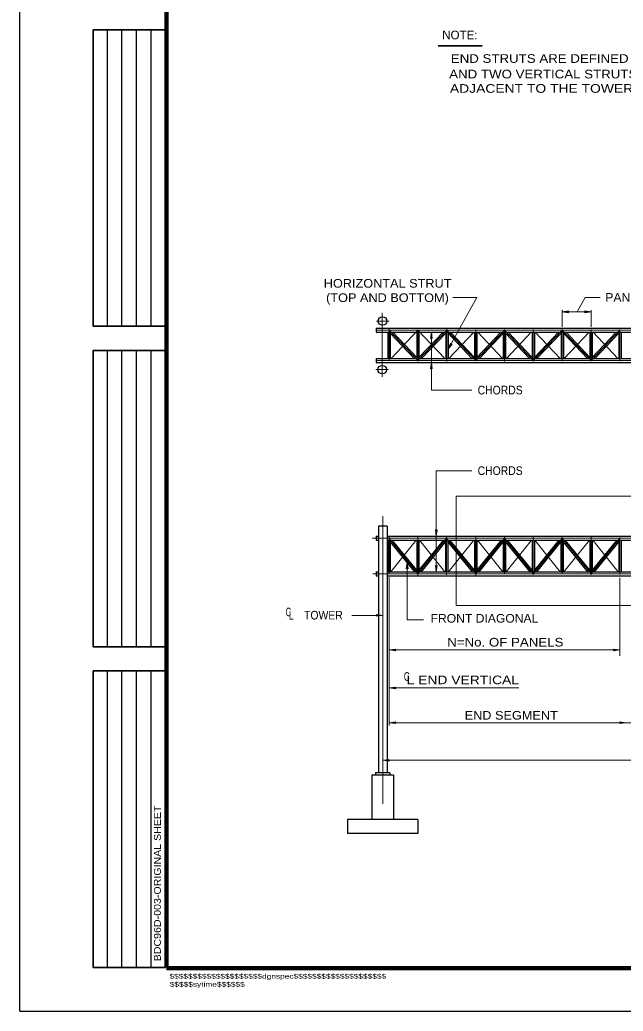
# Model space of a CAD drawing. Extents: x 312601.858 to 312602.699, y 144420.11 to 144420.704.
# Drawn here: x 312601.8579 to 312602.0675, y 144420.1096 to 144420.4541 of the extents above; entities that cross this region are included whole.
import ezdxf
from ezdxf.enums import TextEntityAlignment as Align

# ---------------------------------------------------------------- set-up
doc = ezdxf.new("R2010")
doc.units = 0
doc.header["$LTSCALE"] = 0.0012
doc.linetypes.add('DOT_DASHED', pattern=[7.7, 5, -1.2, 0.3, -1.2])
doc.linetypes.add('LONG_DASHED', pattern=[7.5, 6, -1.5])
for name, color, linetype, lineweight in [('1', 7, 'Continuous', 25), ('2', 7, 'Continuous', 13), ('39', 7, 'Continuous', 13), ('60', 7, 'Continuous', 25)]:
    doc.layers.add(name, color=color, linetype=linetype, lineweight=lineweight)

msp = doc.modelspace()

# ---------------------------------------------------------------- hatches: boundary and pattern name
at = {"layer": '39'}
for points in [[(312602.0484, 144420.3526), (312602.0486, 144420.3523), (312602.0464, 144420.3526), (312602.0486, 144420.3529)], [(312602.0484, 144420.3526), (312602.0486, 144420.3523), (312602.0464, 144420.3526), (312602.0486, 144420.3529)], [(312602.0544, 144420.3526), (312602.0542, 144420.3529), (312602.0564, 144420.3526), (312602.0542, 144420.3523)], [(312602.0009, 144420.3435), (312602.0006, 144420.3433), (312602.0009, 144420.3455), (312602.0012, 144420.3433)], [(312602.0077, 144420.3414), (312602.0081, 144420.3414), (312602.0067, 144420.3396), (312602.0075, 144420.3417)], [(312602.0009, 144420.333), (312602.0006, 144420.3328), (312602.0009, 144420.335), (312602.0012, 144420.3328)], [(312602.0026, 144420.2767), (312602.0029, 144420.2769), (312602.0026, 144420.2747), (312602.0023, 144420.2769)], [(312602.0026, 144420.2643), (312602.0029, 144420.2645), (312602.0026, 144420.2623), (312602.0023, 144420.2645)], [(312601.982, 144420.2471), (312601.9818, 144420.2474), (312601.984, 144420.2471), (312601.9818, 144420.2468)], [(312601.986, 144420.1968), (312601.9862, 144420.1965), (312601.984, 144420.1968), (312601.9862, 144420.1971)]]:
    msp.add_hatch(color=256, dxfattribs=at).paths.add_polyline_path(points)

# ---------------------------------------------------------------- linework, layer by layer
at = {"layer": '1', "lineweight": 35}
msp.add_line((312602.0033, 144420.445), (312602.0186, 144420.445), dxfattribs=at)
at = {"layer": '1', "lineweight": 13}
for p, q in [((312602.0167, 144420.3576), (312602.0067, 144420.3396)), ((312602.0084, 144420.3576), (312602.0167, 144420.3576)), ((312602.0544, 144420.3576), (312602.0516, 144420.3526)), ((312602.0544, 144420.3576), (312602.0596, 144420.3576)), ((312602.0464, 144420.3533), (312602.0464, 144420.3474)), ((312602.0464, 144420.3526), (312602.0564, 144420.3526)), ((312602.0564, 144420.3532), (312602.0564, 144420.3474)), ((312602.0009, 144420.3455), (312602.0009, 144420.3254)), ((312602.066, 144420.3455), (312602.066, 144420.3364)), ((312602.0668, 144420.3455), (312602.0668, 144420.3364)), ((312602.0009, 144420.3254), (312602.015, 144420.3254)), ((312602.0026, 144420.2973), (312602.0026, 144420.2623)), ((312602.0026, 144420.2973), (312602.015, 144420.2973)), ((312602.066, 144420.2733), (312602.066, 144420.2623)), ((312602.0668, 144420.2733), (312602.0668, 144420.2623)), ((312601.9925, 144420.2655), (312601.9925, 144420.2456)), ((312601.9862, 144420.2604), (312601.9862, 144420.2089)), ((312602.0664, 144420.2602), (312602.0664, 144420.2331)), ((312601.9733, 144420.2471), (312601.984, 144420.2471)), ((312601.9749, 144420.2471), (312601.984, 144420.2471)), ((312601.9925, 144420.2456), (312601.9982, 144420.2456)), ((312601.9862, 144420.2351), (312602.0664, 144420.2351)), ((312601.9862, 144420.2219), (312602.0313, 144420.2219)), ((312601.984, 144420.1968), (312602.2376, 144420.1968))]:
    msp.add_line(p, q, dxfattribs=at)
at = {"layer": '1', "linetype": 'DOT_DASHED', "lineweight": 13}
for p, q in [((312601.9838, 144420.3522), (312601.9838, 144420.33)), ((312601.9818, 144420.3494), (312601.9862, 144420.3494)), ((312601.9817, 144420.3462), (312602.2401, 144420.3462)), ((312601.9862, 144420.3466), (312601.9862, 144420.3355)), ((312601.9962, 144420.3464), (312601.9962, 144420.3353)), ((312602.0063, 144420.3466), (312602.0063, 144420.3353)), ((312602.0163, 144420.3464), (312602.0163, 144420.3355)), ((312602.0263, 144420.3465), (312602.0263, 144420.3353)), ((312602.0363, 144420.3465), (312602.0363, 144420.3353)), ((312602.0464, 144420.3465), (312602.0464, 144420.3355)), ((312602.0564, 144420.3465), (312602.0564, 144420.3355)), ((312602.0664, 144420.3464), (312602.0664, 144420.3354)), ((312601.9817, 144420.3357), (312602.2401, 144420.3357)), ((312601.9816, 144420.3325), (312601.986, 144420.3325)), ((312601.984, 144420.2816), (312601.984, 144420.1685)), ((312601.9803, 144420.274), (312602.2399, 144420.274)), ((312601.9862, 144420.2744), (312601.9862, 144420.2614)), ((312601.9962, 144420.2744), (312601.9962, 144420.2611)), ((312602.0062, 144420.2744), (312602.0062, 144420.2612)), ((312602.0163, 144420.2745), (312602.0163, 144420.2611)), ((312602.0263, 144420.2745), (312602.0263, 144420.2615)), ((312602.0363, 144420.2744), (312602.0363, 144420.2612)), ((312602.0463, 144420.2744), (312602.0463, 144420.2614)), ((312602.0564, 144420.2744), (312602.0564, 144420.2612)), ((312602.0664, 144420.2742), (312602.0664, 144420.2613)), ((312601.9806, 144420.2616), (312602.2398, 144420.2616))]:
    msp.add_line(p, q, dxfattribs=at)
at = {"layer": '1'}
for p, q in [((312601.9817, 144420.3469), (312601.9817, 144420.3455)), ((312601.9817, 144420.3469), (312602.2399, 144420.3469)), ((312601.9817, 144420.3455), (312602.2399, 144420.3455)), ((312601.9858, 144420.3455), (312601.9858, 144420.3364)), ((312601.9866, 144420.3455), (312601.9866, 144420.3364)), ((312601.9866, 144420.3452), (312601.9949, 144420.3364)), ((312601.9875, 144420.3455), (312601.9958, 144420.3367)), ((312601.9958, 144420.3455), (312601.9958, 144420.3364)), ((312601.9966, 144420.3367), (312602.005, 144420.3455)), ((312601.9966, 144420.3455), (312601.9966, 144420.3364)), ((312601.9975, 144420.3364), (312602.0059, 144420.3452)), ((312602.0059, 144420.3455), (312602.0059, 144420.3364)), ((312602.0067, 144420.3455), (312602.0067, 144420.3364)), ((312602.0067, 144420.3452), (312602.015, 144420.3364)), ((312602.0076, 144420.3455), (312602.0159, 144420.3367)), ((312602.0159, 144420.3455), (312602.0159, 144420.3364)), ((312602.0167, 144420.3367), (312602.025, 144420.3455)), ((312602.0167, 144420.3455), (312602.0167, 144420.3364)), ((312602.0176, 144420.3364), (312602.0259, 144420.3452)), ((312602.0259, 144420.3455), (312602.0259, 144420.3364)), ((312602.0267, 144420.3455), (312602.0267, 144420.3364)), ((312602.0267, 144420.3452), (312602.035, 144420.3364)), ((312602.0276, 144420.3455), (312602.0359, 144420.3367)), ((312602.0359, 144420.3455), (312602.0359, 144420.3364)), ((312602.0367, 144420.3367), (312602.0451, 144420.3455)), ((312602.0367, 144420.3455), (312602.0367, 144420.3364)), ((312602.0376, 144420.3364), (312602.046, 144420.3452)), ((312602.046, 144420.3455), (312602.046, 144420.3364)), ((312602.0468, 144420.3455), (312602.0468, 144420.3364)), ((312602.0468, 144420.3452), (312602.0551, 144420.3364)), ((312602.0477, 144420.3455), (312602.056, 144420.3367)), ((312602.056, 144420.3455), (312602.056, 144420.3364)), ((312602.0568, 144420.3367), (312602.0651, 144420.3455)), ((312602.0568, 144420.3455), (312602.0568, 144420.3364)), ((312602.0577, 144420.3364), (312602.066, 144420.3452)), ((312602.066, 144420.3455), (312602.066, 144420.3364)), ((312602.0668, 144420.3455), (312602.0668, 144420.3364)), ((312601.9817, 144420.3364), (312601.9817, 144420.335)), ((312601.9817, 144420.3364), (312602.2399, 144420.3364)), ((312601.9817, 144420.335), (312602.2399, 144420.335)), ((312601.9855, 144420.2781), (312601.9825, 144420.2781)), ((312601.9825, 144420.2781), (312601.9825, 144420.1924)), ((312601.9855, 144420.2781), (312601.9855, 144420.1924)), ((312601.9817, 144420.2747), (312601.9825, 144420.2747)), ((312601.9817, 144420.2747), (312601.9817, 144420.2733)), ((312601.9817, 144420.2733), (312601.9825, 144420.2733)), ((312601.9855, 144420.2747), (312602.2361, 144420.2747)), ((312601.9855, 144420.2733), (312602.2361, 144420.2733)), ((312601.9858, 144420.2733), (312601.9858, 144420.2623)), ((312601.9866, 144420.2733), (312601.9866, 144420.2623)), ((312601.9951, 144420.2623), (312601.9866, 144420.2728)), ((312601.9958, 144420.2628), (312601.9873, 144420.2733)), ((312601.9958, 144420.2733), (312601.9958, 144420.2623)), ((312601.9966, 144420.2733), (312601.9966, 144420.2623)), ((312602.0051, 144420.2733), (312601.9966, 144420.2628)), ((312602.0058, 144420.2728), (312601.9973, 144420.2623)), ((312602.0058, 144420.2733), (312602.0058, 144420.2623)), ((312602.0066, 144420.2733), (312602.0066, 144420.2623)), ((312602.0152, 144420.2623), (312602.0066, 144420.2728)), ((312602.0159, 144420.2628), (312602.0073, 144420.2733)), ((312602.0159, 144420.2733), (312602.0159, 144420.2623)), ((312602.0167, 144420.2733), (312602.0167, 144420.2623)), ((312602.0252, 144420.2733), (312602.0167, 144420.2628)), ((312602.0259, 144420.2728), (312602.0174, 144420.2623)), ((312602.0259, 144420.2733), (312602.0259, 144420.2623)), ((312602.0267, 144420.2733), (312602.0267, 144420.2623)), ((312602.0352, 144420.2623), (312602.0267, 144420.2728)), ((312602.0359, 144420.2628), (312602.0274, 144420.2733)), ((312602.0359, 144420.2733), (312602.0359, 144420.2623)), ((312602.0367, 144420.2733), (312602.0367, 144420.2623)), ((312602.0452, 144420.2733), (312602.0367, 144420.2628)), ((312602.0459, 144420.2728), (312602.0374, 144420.2623)), ((312602.0459, 144420.2733), (312602.0459, 144420.2623)), ((312602.0467, 144420.2733), (312602.0467, 144420.2623)), ((312602.0553, 144420.2623), (312602.0467, 144420.2728)), ((312602.056, 144420.2628), (312602.0474, 144420.2733)), ((312602.056, 144420.2733), (312602.056, 144420.2623)), ((312602.0568, 144420.2733), (312602.0568, 144420.2623)), ((312602.0653, 144420.2733), (312602.0568, 144420.2628)), ((312602.066, 144420.2728), (312602.0575, 144420.2623)), ((312602.066, 144420.2733), (312602.066, 144420.2623)), ((312602.0668, 144420.2733), (312602.0668, 144420.2623)), ((312601.9817, 144420.2623), (312601.9817, 144420.2609)), ((312601.9817, 144420.2623), (312601.9825, 144420.2623)), ((312601.9817, 144420.2609), (312601.9825, 144420.2609)), ((312601.9855, 144420.2623), (312602.2361, 144420.2623)), ((312601.9855, 144420.2609), (312602.2361, 144420.2609)), ((312601.9878, 144420.1916), (312601.9802, 144420.1916)), ((312601.9802, 144420.1916), (312601.9802, 144420.1762)), ((312601.9865, 144420.1924), (312601.9815, 144420.1924)), ((312601.9815, 144420.1924), (312601.9815, 144420.1916)), ((312601.9865, 144420.1924), (312601.9865, 144420.1916)), ((312601.9878, 144420.1916), (312601.9878, 144420.1762)), ((312601.9962, 144420.1762), (312601.9718, 144420.1762)), ((312601.9718, 144420.1762), (312601.9718, 144420.1713)), ((312601.9962, 144420.1762), (312601.9962, 144420.1713)), ((312601.9962, 144420.1713), (312601.9718, 144420.1713))]:
    msp.add_line(p, q, dxfattribs=at)
at = {"layer": '1', "linetype": 'LONG_DASHED', "lineweight": 13}
for p, q in [((312601.9869, 144420.3364), (312601.9962, 144420.3462)), ((312601.9962, 144420.3462), (312602.0056, 144420.3364)), ((312602.007, 144420.3364), (312602.0156, 144420.3455)), ((312602.017, 144420.3455), (312602.0256, 144420.3364)), ((312602.027, 144420.3364), (312602.0356, 144420.3455)), ((312602.037, 144420.3455), (312602.0457, 144420.3364)), ((312602.0471, 144420.3364), (312602.0557, 144420.3455)), ((312602.0571, 144420.3455), (312602.0657, 144420.3364)), ((312602.0095, 144420.2885), (312602.2131, 144420.2885)), ((312602.0095, 144420.2885), (312602.0095, 144420.2506)), ((312601.9956, 144420.2733), (312601.9868, 144420.2623)), ((312602.0056, 144420.2623), (312601.9968, 144420.2733)), ((312602.0157, 144420.2733), (312602.0068, 144420.2623)), ((312602.0257, 144420.2623), (312602.0169, 144420.2733)), ((312602.0357, 144420.2733), (312602.0269, 144420.2623)), ((312602.0457, 144420.2623), (312602.0369, 144420.2733)), ((312602.0558, 144420.2733), (312602.0469, 144420.2623)), ((312602.0658, 144420.2623), (312602.057, 144420.2733)), ((312602.0095, 144420.2506), (312602.2131, 144420.2506))]:
    msp.add_line(p, q, dxfattribs=at)
at = {"layer": '1', "linetype": 'DOT_DASHED', "lineweight": 13}
for points in [[(312601.9862, 144420.3462), (312601.9962, 144420.3357), (312602.0063, 144420.3462), (312602.0163, 144420.3357), (312602.0263, 144420.3462), (312602.0363, 144420.3357), (312602.0464, 144420.3462), (312602.0564, 144420.3357), (312602.0664, 144420.3462)], [(312602.0664, 144420.274), (312602.0564, 144420.2616), (312602.0463, 144420.274), (312602.0363, 144420.2616), (312602.0263, 144420.274), (312602.0163, 144420.2616), (312602.0062, 144420.274), (312601.9962, 144420.2616), (312601.9862, 144420.274)]]:
    msp.add_lwpolyline(points, dxfattribs=at)
at = {"layer": '1', "lineweight": 13}
for points in [[(312601.9922, 144420.2633), (312601.9925, 144420.2655), (312601.9928, 144420.2633), (312601.9925, 144420.2635)], [(312601.9885, 144420.2348), (312601.9862, 144420.2351), (312601.9885, 144420.2354), (312601.9882, 144420.2351)], [(312602.0642, 144420.2354), (312602.0664, 144420.2351), (312602.0642, 144420.2348), (312602.0644, 144420.2351)], [(312601.9885, 144420.2216), (312601.9862, 144420.2219), (312601.9885, 144420.2222), (312601.9882, 144420.2219)], [(312601.9885, 144420.2095), (312601.9862, 144420.2098), (312601.9885, 144420.2101), (312601.9882, 144420.2098)], [(312602.0664, 144420.2101), (312602.0686, 144420.2098), (312602.0664, 144420.2095), (312602.0666, 144420.2098)]]:
    msp.add_lwpolyline(points, close=True, dxfattribs=at)
at = {"layer": '1'}
for centre in [(312601.9839, 144420.3494), (312601.9838, 144420.3325)]:
    msp.add_circle(centre, 0.0015, dxfattribs=at)
at = {"layer": '1', "lineweight": 13}
msp.add_open_spline([(312601.9862, 144420.2098), (312602.2354, 144420.2098)], degree=1, dxfattribs=at)
at = {"layer": '39', "lineweight": 25}
msp.add_line((312601.8579, 144420.1096), (312601.8579, 144420.7036), dxfattribs=at)
msp.add_lwpolyline([(312601.8579, 144420.1096), (312602.6989, 144420.1096), (312602.6989, 144420.7036)], dxfattribs=at)
at = {"layer": '39', "lineweight": 158}
for points in [[(312601.9089, 144420.1246), (312602.6839, 144420.1246), (312602.6839, 144420.6646)], [(312601.9089, 144420.1248), (312601.9089, 144420.6646), (312602.6839, 144420.6646)]]:
    msp.add_lwpolyline(points, dxfattribs=at)
at = {"layer": '39'}
for points in [[(312602.0484, 144420.3526), (312602.0486, 144420.3523), (312602.0464, 144420.3526), (312602.0486, 144420.3529)], [(312602.0484, 144420.3526), (312602.0486, 144420.3523), (312602.0464, 144420.3526), (312602.0486, 144420.3529)], [(312602.0544, 144420.3526), (312602.0542, 144420.3529), (312602.0564, 144420.3526), (312602.0542, 144420.3523)], [(312602.0009, 144420.3435), (312602.0006, 144420.3433), (312602.0009, 144420.3455), (312602.0012, 144420.3433)], [(312602.0077, 144420.3414), (312602.0081, 144420.3414), (312602.0067, 144420.3396), (312602.0075, 144420.3417)], [(312602.0009, 144420.333), (312602.0006, 144420.3328), (312602.0009, 144420.335), (312602.0012, 144420.3328)], [(312602.0026, 144420.2767), (312602.0029, 144420.2769), (312602.0026, 144420.2747), (312602.0023, 144420.2769)], [(312602.0026, 144420.2643), (312602.0029, 144420.2645), (312602.0026, 144420.2623), (312602.0023, 144420.2645)], [(312601.982, 144420.2471), (312601.9818, 144420.2474), (312601.984, 144420.2471), (312601.9818, 144420.2468)], [(312601.986, 144420.1968), (312601.9862, 144420.1965), (312601.984, 144420.1968), (312601.9862, 144420.1971)]]:
    msp.add_lwpolyline(points, close=True, dxfattribs=at)
at = {"layer": '60'}
for p, q in [((312601.8884, 144420.3476), (312601.8884, 144420.4506)), ((312601.8934, 144420.3476), (312601.8934, 144420.4506)), ((312601.8984, 144420.3476), (312601.8984, 144420.4506)), ((312601.9035, 144420.3476), (312601.9035, 144420.4506)), ((312601.8884, 144420.2362), (312601.8884, 144420.3392)), ((312601.8934, 144420.2362), (312601.8934, 144420.3392)), ((312601.8984, 144420.2362), (312601.8984, 144420.3392)), ((312601.9035, 144420.2362), (312601.9035, 144420.3392)), ((312601.8884, 144420.1248), (312601.8884, 144420.2278)), ((312601.8934, 144420.1248), (312601.8934, 144420.2278)), ((312601.8984, 144420.1248), (312601.8984, 144420.2278)), ((312601.9035, 144420.1248), (312601.9035, 144420.2278))]:
    msp.add_line(p, q, dxfattribs=at)
at = {"layer": '60', "lineweight": 35}
for points in [[(312601.9085, 144420.3476), (312601.8834, 144420.3476), (312601.8834, 144420.4506), (312601.9085, 144420.4506)], [(312601.9085, 144420.2362), (312601.8834, 144420.2362), (312601.8834, 144420.3392), (312601.9085, 144420.3392)], [(312601.9085, 144420.1248), (312601.8834, 144420.1248), (312601.8834, 144420.2278), (312601.9085, 144420.2278)]]:
    msp.add_lwpolyline(points, dxfattribs=at)

# ---------------------------------------------------------------- texts
at = {"layer": '1'}
msp.add_text('NOTE:', height=0.003, dxfattribs=at).set_placement((312602.0108, 144420.4473), align=Align.CENTER)
for s, width, p in [('HORIZONTAL STRUT', 1.1, (312601.9857, 144420.361)), ('(TOP AND BOTTOM)', 1.1, (312601.98565, 144420.356)), ('C', 0.7, (312601.99235, 144420.2244)), ('L END VERTICAL ', 1.2, (312602.0125, 144420.2232)), ('END SEGMENT', 1.1, (312602.02865, 144420.2109))]:
    msp.add_text(s, height=0.003, dxfattribs=dict(at, width=width)).set_placement(p, align=Align.CENTER)
at = {"layer": '2'}
for s, width, p in [('END STRUTS ARE DEFINED AS THE TWO HORIZONTAL', 1.15, (312602.06905, 144420.4391)), ('AND TWO VERTICAL STRUTS LOCATED IMMEDIATELY', 1.15, (312602.0676, 144420.4337)), ('ADJACENT TO THE TOWERS (SEE PLATE 2.9-5).', 1.2, (312602.063, 144420.4287)), ('PANEL WIDTH', 1.05, (312602.07575, 144420.3561)), ('CHORDS', 0.9, (312602.0248, 144420.3239)), ('CHORDS', 0.9, (312602.0248, 144420.2959)), ('C', 0.6, (312601.9512, 144420.2468)), ('L', 0.75, (312601.95225, 144420.2456)), ('TOWER', 0.9, (312601.9634, 144420.2457)), ('FRONT DIAGONAL', 1.05, (312602.01935, 144420.2446)), ('N=No. OF PANELS', 1.15, (312602.0266, 144420.2363))]:
    msp.add_text(s, height=0.003, dxfattribs=dict(at, width=width)).set_placement(p, align=Align.CENTER)
at = {"layer": '2', "width": 1.15}
msp.add_text('BDC96D-003-ORIGINAL SHEET', height=0.0024, rotation=90, dxfattribs=at).set_placement((312601.9069, 144420.154), align=Align.CENTER)
at = {"layer": '2', "width": 1.3}
for s, p in [('$$$$$$$$$$$$$$$$$$$$dgnspec$$$$$$$$$$$$$$$$$$$$', (312601.9099, 144420.1209)), ('$$$$$sytime$$$$$$', (312601.91, 144420.1181))]:
    msp.add_text(s, height=0.001664, dxfattribs=at).set_placement(p)

doc.saveas('drawing.dxf')
